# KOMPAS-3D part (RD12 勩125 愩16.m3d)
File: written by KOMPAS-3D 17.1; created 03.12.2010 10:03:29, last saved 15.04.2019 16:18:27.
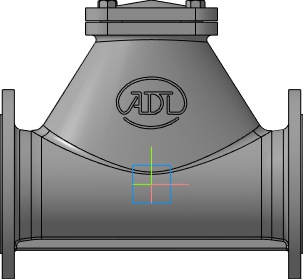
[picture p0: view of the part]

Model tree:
1. Плоскость XY
2. Плоскость ZX
3. Плоскость ZY
4. Ось X
5. Ось Y
6. Ось Z
7. Начало координат
8. Операция без истории:2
